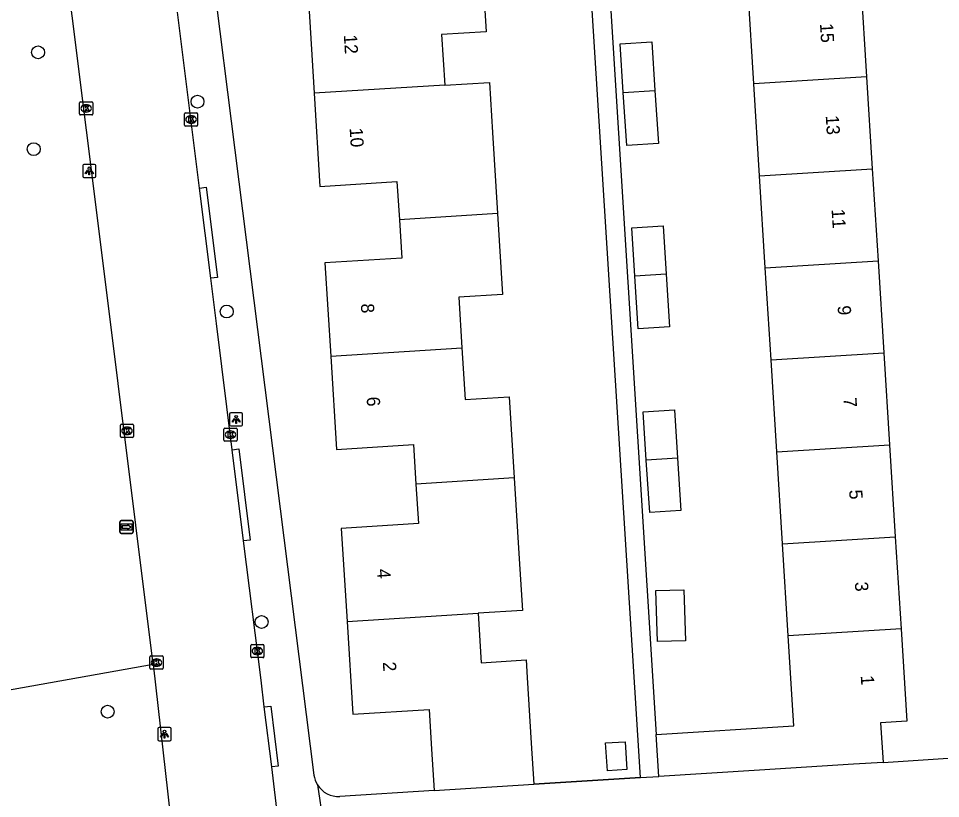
# Model space of a CAD drawing. Extents: x 159689 to 160786, y 387323 to 388339.
# Drawn here: x 160150.5 to 160220.6, y 388068.8 to 388128 of the extents above; entities that cross this region are included whole.
import ezdxf

# ---------------------------------------------------------------- set-up
doc = ezdxf.new("R2010")
doc.units = 0
for name, color, linetype in [('IMGEO_Berm_groen', 7, 'Continuous'), ('IMGEO_Boom', 7, 'Continuous'), ('IMGEO_Kolk', 7, 'Continuous'), ('IMGEO_Lichtpunt', 7, 'Continuous'), ('IMGEO_Muur', 7, 'Continuous'), ('IMGEO_Pand', 7, 'Continuous'), ('IMGEO_Pand_nummerreeks', 7, 'Continuous'), ('IMGEO_Rijbaan_lokaal_gesloten', 7, 'Continuous'), ('IMGEO_Voetpad_open', 7, 'Continuous'), ('IMGEO_Wegwijzer', 7, 'Continuous')]:
    doc.layers.add(name, color=color, linetype=linetype)

msp = doc.modelspace()

# ---------------------------------------------------------------- linework, layer by layer
at = {"layer": 'IMGEO_Berm_groen'}
msp.add_lwpolyline([(160145.16, 388076.181), (160160.785, 388078.981)], dxfattribs=at)
at = {"layer": 'IMGEO_Boom'}
for centre in [(160152.037, 388125.433), (160164.139, 388121.692), (160151.709, 388118.086), (160166.361, 388105.751), (160169.007, 388082.18), (160157.319, 388075.366)]:
    msp.add_circle(centre, 0.489, dxfattribs=at)
at = {"layer": 'IMGEO_Kolk'}
for p, q in [((160155.184, 388120.753), (160155.184, 388121.605)), ((160155.259, 388121.679), (160156.111, 388121.679)), ((160155.672, 388121.459), (160155.697, 388121.459)), ((160156.185, 388121.605), (160156.185, 388120.753)), ((160156.111, 388120.679), (160155.259, 388120.679)), ((160155.695, 388120.899), (160155.67, 388120.899)), ((160163.152, 388119.91), (160163.152, 388120.762)), ((160163.227, 388120.836), (160164.079, 388120.836)), ((160163.64, 388120.616), (160163.665, 388120.616)), ((160164.153, 388120.762), (160164.153, 388119.91)), ((160164.079, 388119.836), (160163.227, 388119.836)), ((160163.663, 388120.056), (160163.638, 388120.056)), ((160158.29, 388096.267), (160158.29, 388097.119)), ((160158.365, 388097.193), (160159.217, 388097.193)), ((160158.778, 388096.973), (160158.803, 388096.973)), ((160159.291, 388097.119), (160159.291, 388096.267)), ((160166.144, 388095.976), (160166.144, 388096.828)), ((160166.219, 388096.902), (160167.071, 388096.902)), ((160167.145, 388096.828), (160167.145, 388095.976)), ((160159.217, 388096.193), (160158.365, 388096.193)), ((160158.801, 388096.413), (160158.776, 388096.413)), ((160166.655, 388096.122), (160166.63, 388096.122)), ((160166.632, 388096.682), (160166.657, 388096.682)), ((160167.071, 388095.902), (160166.219, 388095.902)), ((160168.187, 388079.543), (160168.187, 388080.395)), ((160168.262, 388080.469), (160169.114, 388080.469)), ((160168.675, 388080.249), (160168.7, 388080.249)), ((160169.188, 388080.395), (160169.188, 388079.543)), ((160160.527, 388078.669), (160160.527, 388079.521)), ((160160.602, 388079.595), (160161.454, 388079.595)), ((160161.015, 388079.375), (160161.04, 388079.375)), ((160161.528, 388079.521), (160161.528, 388078.669)), ((160169.114, 388079.469), (160168.262, 388079.469)), ((160168.698, 388079.689), (160168.673, 388079.689)), ((160161.454, 388078.595), (160160.602, 388078.595)), ((160161.038, 388078.815), (160161.013, 388078.815))]:
    msp.add_line(p, q, dxfattribs=at)
for points in [[(160155.184, 388120.753), (160155.184, 388121.605)], [(160155.259, 388121.679), (160156.111, 388121.679)], [(160155.505, 388121.379), (160155.628, 388121.379), (160155.628, 388121.228), (160155.758, 388121.379), (160155.922, 388121.379), (160155.776, 388121.228), (160155.929, 388120.979), (160155.777, 388120.979), (160155.692, 388121.143), (160155.628, 388121.076), (160155.628, 388120.979), (160155.505, 388120.979), (160155.505, 388121.379)], [(160156.185, 388121.605), (160156.185, 388120.753)], [(160156.111, 388120.679), (160155.259, 388120.679)], [(160163.152, 388119.91), (160163.152, 388120.762)], [(160163.227, 388120.836), (160164.079, 388120.836)], [(160163.473, 388120.536), (160163.596, 388120.536), (160163.596, 388120.385), (160163.726, 388120.536), (160163.89, 388120.536), (160163.744, 388120.385), (160163.897, 388120.136), (160163.745, 388120.136), (160163.66, 388120.3), (160163.596, 388120.233), (160163.596, 388120.136), (160163.473, 388120.136), (160163.473, 388120.536)], [(160164.153, 388120.762), (160164.153, 388119.91)], [(160164.079, 388119.836), (160163.227, 388119.836)], [(160158.29, 388096.267), (160158.29, 388097.119)], [(160158.365, 388097.193), (160159.217, 388097.193)], [(160158.611, 388096.893), (160158.734, 388096.893), (160158.734, 388096.742), (160158.864, 388096.893), (160159.028, 388096.893), (160158.882, 388096.742), (160159.035, 388096.493), (160158.883, 388096.493), (160158.798, 388096.657), (160158.734, 388096.59), (160158.734, 388096.493), (160158.611, 388096.493), (160158.611, 388096.893)], [(160159.291, 388097.119), (160159.291, 388096.267)], [(160166.144, 388095.976), (160166.144, 388096.828)], [(160166.219, 388096.902), (160167.071, 388096.902)], [(160167.145, 388096.828), (160167.145, 388095.976)], [(160159.217, 388096.193), (160158.365, 388096.193)], [(160166.465, 388096.602), (160166.588, 388096.602), (160166.588, 388096.451), (160166.718, 388096.602), (160166.882, 388096.602), (160166.736, 388096.451), (160166.889, 388096.202), (160166.737, 388096.202), (160166.652, 388096.366), (160166.588, 388096.299), (160166.588, 388096.202), (160166.465, 388096.202), (160166.465, 388096.602)], [(160167.071, 388095.902), (160166.219, 388095.902)], [(160168.187, 388079.543), (160168.187, 388080.395)], [(160168.262, 388080.469), (160169.114, 388080.469)], [(160168.508, 388080.169), (160168.631, 388080.169), (160168.631, 388080.018), (160168.761, 388080.169), (160168.925, 388080.169), (160168.779, 388080.018), (160168.932, 388079.769), (160168.78, 388079.769), (160168.695, 388079.933), (160168.631, 388079.866), (160168.631, 388079.769), (160168.508, 388079.769), (160168.508, 388080.169)], [(160169.188, 388080.395), (160169.188, 388079.543)], [(160160.527, 388078.669), (160160.527, 388079.521)], [(160160.602, 388079.595), (160161.454, 388079.595)], [(160160.848, 388079.295), (160160.971, 388079.295), (160160.971, 388079.144), (160161.101, 388079.295), (160161.265, 388079.295), (160161.119, 388079.144), (160161.272, 388078.895), (160161.12, 388078.895), (160161.035, 388079.059), (160160.971, 388078.992), (160160.971, 388078.895), (160160.848, 388078.895), (160160.848, 388079.295)], [(160161.528, 388079.521), (160161.528, 388078.669)], [(160169.114, 388079.469), (160168.262, 388079.469)], [(160161.454, 388078.595), (160160.602, 388078.595)]]:
    msp.add_lwpolyline(points, dxfattribs=at)
for centre, start, end in [((160155.261, 388121.603), 91.55205, 178.44795), ((160155.261, 388121.603), 91.55205, 178.44795), ((160156.109, 388121.603), 1.55205, 88.44795), ((160156.109, 388121.603), 1.55205, 88.44795), ((160155.261, 388120.755), 181.55205, 268.44795), ((160155.261, 388120.755), 181.55205, 268.44795), ((160156.109, 388120.755), 271.55205, 358.44795), ((160156.109, 388120.755), 271.55205, 358.44795), ((160163.229, 388120.76), 91.55205, 178.44795), ((160163.229, 388120.76), 91.55205, 178.44795), ((160164.077, 388120.76), 1.55205, 88.44795), ((160164.077, 388120.76), 1.55205, 88.44795), ((160163.229, 388119.912), 181.55205, 268.44795), ((160163.229, 388119.912), 181.55205, 268.44795), ((160164.077, 388119.912), 271.55205, 358.44795), ((160164.077, 388119.912), 271.55205, 358.44795), ((160158.367, 388097.117), 91.55205, 178.44795), ((160158.367, 388097.117), 91.55205, 178.44795), ((160159.215, 388097.117), 1.55205, 88.44795), ((160159.215, 388097.117), 1.55205, 88.44795), ((160166.221, 388096.826), 91.55205, 178.44795), ((160166.221, 388096.826), 91.55205, 178.44795), ((160167.069, 388096.826), 1.55205, 88.44795), ((160167.069, 388096.826), 1.55205, 88.44795), ((160158.367, 388096.269), 181.55205, 268.44795), ((160158.367, 388096.269), 181.55205, 268.44795), ((160159.215, 388096.269), 271.55205, 358.44795), ((160159.215, 388096.269), 271.55205, 358.44795), ((160166.221, 388095.978), 181.55205, 268.44795), ((160166.221, 388095.978), 181.55205, 268.44795), ((160167.069, 388095.978), 271.55205, 358.44795), ((160167.069, 388095.978), 271.55205, 358.44795), ((160168.264, 388080.393), 91.55205, 178.44795), ((160168.264, 388080.393), 91.55205, 178.44795), ((160169.112, 388080.393), 1.55205, 88.44795), ((160169.112, 388080.393), 1.55205, 88.44795), ((160160.604, 388079.519), 91.55205, 178.44795), ((160160.604, 388079.519), 91.55205, 178.44795), ((160161.452, 388079.519), 1.55205, 88.44795), ((160161.452, 388079.519), 1.55205, 88.44795), ((160168.264, 388079.545), 181.55205, 268.44795), ((160168.264, 388079.545), 181.55205, 268.44795), ((160169.112, 388079.545), 271.55205, 358.44795), ((160169.112, 388079.545), 271.55205, 358.44795), ((160160.604, 388078.671), 181.55205, 268.44795), ((160160.604, 388078.671), 181.55205, 268.44795), ((160161.452, 388078.671), 271.55205, 358.44795), ((160161.452, 388078.671), 271.55205, 358.44795)]:
    msp.add_arc(centre, 0.0765, start, end, dxfattribs=at)
for centre, major_axis, ratio, start_param, end_param in [((160155.671, 388121.179), (-0.387, 0.002), 0.722429, 4.712389, 7.853982), ((160155.696, 388121.179), (-0.39, 0.002), 0.717154, 1.570796, 4.712389), ((160163.639, 388120.336), (-0.387, 0.002), 0.722429, 4.712389, 7.853982), ((160163.664, 388120.336), (-0.39, 0.002), 0.717154, 1.570796, 4.712389), ((160158.777, 388096.693), (-0.387, 0.002), 0.722429, 4.712389, 7.853982), ((160158.802, 388096.693), (-0.39, 0.002), 0.717154, 1.570796, 4.712389), ((160166.631, 388096.402), (-0.387, 0.002), 0.722429, 4.712389, 7.853982), ((160166.656, 388096.402), (-0.39, 0.002), 0.717154, 1.570796, 4.712389), ((160168.674, 388079.969), (-0.387, 0.002), 0.722429, 4.712389, 7.853982), ((160168.699, 388079.969), (-0.39, 0.002), 0.717154, 1.570796, 4.712389), ((160161.014, 388079.095), (-0.387, 0.002), 0.722429, 4.712389, 7.853982), ((160161.039, 388079.095), (-0.39, 0.002), 0.717154, 1.570796, 4.712389)]:
    msp.add_ellipse(centre, major_axis=major_axis, ratio=ratio, start_param=start_param, end_param=end_param, dxfattribs=at)
at = {"layer": 'IMGEO_Lichtpunt'}
for p, q in [((160155.426, 388116.831), (160155.426, 388116.024)), ((160155.426, 388116.831), (160155.426, 388116.024)), ((160156.328, 388116.926), (160155.52, 388116.926)), ((160156.328, 388116.926), (160155.52, 388116.926)), ((160156.422, 388116.024), (160156.422, 388116.831)), ((160156.422, 388116.024), (160156.422, 388116.831)), ((160155.52, 388115.93), (160156.328, 388115.93)), ((160155.52, 388115.93), (160156.328, 388115.93)), ((160166.574, 388097.967), (160166.574, 388097.16)), ((160166.574, 388097.967), (160166.574, 388097.16)), ((160167.476, 388098.062), (160166.668, 388098.062)), ((160167.476, 388098.062), (160166.668, 388098.062)), ((160167.57, 388097.16), (160167.57, 388097.967)), ((160167.57, 388097.16), (160167.57, 388097.967)), ((160166.668, 388097.066), (160167.476, 388097.066)), ((160166.668, 388097.066), (160167.476, 388097.066)), ((160161.139, 388074.062), (160161.139, 388073.255)), ((160161.139, 388074.062), (160161.139, 388073.255)), ((160162.041, 388074.157), (160161.233, 388074.157)), ((160162.041, 388074.157), (160161.233, 388074.157)), ((160162.135, 388073.255), (160162.135, 388074.062)), ((160162.135, 388073.255), (160162.135, 388074.062)), ((160161.233, 388073.161), (160162.041, 388073.161)), ((160161.233, 388073.161), (160162.041, 388073.161))]:
    msp.add_line(p, q, dxfattribs=at)
for points in [[(160155.8, 388116.495), (160155.839, 388116.467), (160155.651, 388116.205), (160155.613, 388116.232), (160155.8, 388116.495)], [(160155.902, 388116.447), (160155.949, 388116.447), (160155.949, 388116.125), (160155.902, 388116.125), (160155.902, 388116.447)], [(160156.012, 388116.467), (160156.05, 388116.494), (160156.237, 388116.232), (160156.198, 388116.204), (160156.012, 388116.467)], [(160166.948, 388097.631), (160166.987, 388097.603), (160166.799, 388097.341), (160166.761, 388097.368), (160166.948, 388097.631)], [(160167.05, 388097.583), (160167.097, 388097.583), (160167.097, 388097.261), (160167.05, 388097.261), (160167.05, 388097.583)], [(160167.16, 388097.603), (160167.198, 388097.63), (160167.385, 388097.368), (160167.346, 388097.34), (160167.16, 388097.603)], [(160161.513, 388073.726), (160161.552, 388073.698), (160161.364, 388073.436), (160161.326, 388073.463), (160161.513, 388073.726)], [(160161.615, 388073.678), (160161.662, 388073.678), (160161.662, 388073.356), (160161.615, 388073.356), (160161.615, 388073.678)], [(160161.725, 388073.698), (160161.763, 388073.725), (160161.95, 388073.463), (160161.911, 388073.435), (160161.725, 388073.698)]]:
    msp.add_lwpolyline(points, dxfattribs=at)
for centre in [(160155.925, 388116.629), (160167.073, 388097.765), (160161.638, 388073.86)]:
    msp.add_circle(centre, 0.0994, dxfattribs=at)
for centre, start, end in [((160155.52, 388116.831), 90, 180), ((160155.52, 388116.831), 90, 180), ((160156.328, 388116.831), 0, 90), ((160156.328, 388116.831), 0, 90), ((160155.52, 388116.024), 180, 270), ((160155.52, 388116.024), 180, 270), ((160156.328, 388116.024), 270, 0), ((160156.328, 388116.024), 270, 360), ((160166.668, 388097.967), 90, 180), ((160166.668, 388097.967), 90, 180), ((160167.476, 388097.967), 0, 90), ((160167.476, 388097.967), 0, 90), ((160166.668, 388097.16), 180, 270), ((160166.668, 388097.16), 180, 270), ((160167.476, 388097.16), 270, 0), ((160167.476, 388097.16), 270, 360), ((160161.233, 388074.062), 90, 180), ((160161.233, 388074.062), 90, 180), ((160162.041, 388074.062), 0, 90), ((160162.041, 388074.062), 0, 90), ((160161.233, 388073.255), 180, 270), ((160161.233, 388073.255), 180, 270), ((160162.041, 388073.255), 270, 0), ((160162.041, 388073.255), 270, 360)]:
    msp.add_arc(centre, 0.0946, start, end, dxfattribs=at)
at = {"layer": 'IMGEO_Muur'}
msp.add_lwpolyline([(160197.779, 388070.357), (160189.678, 388069.849)], dxfattribs=at)
at = {"layer": 'IMGEO_Pand'}
for points in [[(160185.677, 388133.171), (160186.062, 388126.992), (160182.674, 388126.781), (160182.913, 388122.946)], [(160178.211, 388132.708), (160178.394, 388129.769), (160172.559, 388129.405), (160172.999, 388122.33)], [(160206.378, 388123.038), (160205.94, 388130.05), (160209.512, 388130.274), (160214.502, 388130.586), (160214.94, 388123.574)], [(160196.473, 388122.38), (160196.235, 388126.074), (160198.637, 388126.229), (160198.876, 388122.531)], [(160214.94, 388123.574), (160206.378, 388123.038)], [(160214.94, 388123.574), (160215.377, 388116.587)], [(160182.913, 388122.946), (160172.999, 388122.33)], [(160182.913, 388122.946), (160186.307, 388123.157), (160186.544, 388119.347), (160186.928, 388113.187)], [(160206.815, 388116.051), (160206.378, 388123.038)], [(160172.999, 388122.33), (160173.439, 388115.257), (160179.287, 388115.621), (160179.467, 388112.718)], [(160198.876, 388122.531), (160199.136, 388118.503), (160196.734, 388118.348), (160196.473, 388122.38)], [(160196.473, 388122.38), (160198.876, 388122.531)], [(160206.815, 388116.051), (160215.377, 388116.587)], [(160215.377, 388116.587), (160215.814, 388109.601)], [(160207.252, 388109.065), (160206.815, 388116.051)], [(160186.928, 388113.187), (160179.467, 388112.718)], [(160186.928, 388113.187), (160187.31, 388107.056), (160183.978, 388106.848), (160184.218, 388102.99)], [(160179.467, 388112.718), (160179.648, 388109.815), (160173.821, 388109.452), (160174.262, 388102.368)], [(160197.345, 388108.445), (160197.109, 388112.101), (160199.491, 388112.255), (160199.727, 388108.594)], [(160207.252, 388109.065), (160215.814, 388109.601)], [(160215.814, 388109.601), (160216.251, 388102.615)], [(160199.727, 388108.594), (160199.985, 388104.587), (160197.604, 388104.433), (160197.345, 388108.445)], [(160199.727, 388108.594), (160197.345, 388108.445)], [(160207.689, 388102.079), (160207.252, 388109.065)], [(160174.262, 388102.368), (160184.218, 388102.99)], [(160174.262, 388102.368), (160174.703, 388095.284), (160180.542, 388095.648), (160180.728, 388092.65)], [(160184.218, 388102.99), (160184.462, 388099.079), (160187.801, 388099.286), (160188.185, 388093.116)], [(160207.689, 388102.079), (160216.251, 388102.615)], [(160216.251, 388102.615), (160216.688, 388095.628)], [(160208.126, 388095.092), (160207.689, 388102.079)], [(160198.219, 388094.472), (160197.983, 388098.128), (160200.357, 388098.281), (160200.593, 388094.62)], [(160208.126, 388095.092), (160216.688, 388095.628)], [(160216.688, 388095.628), (160217.125, 388088.642)], [(160200.593, 388094.62), (160200.85, 388090.641), (160198.476, 388090.488), (160198.219, 388094.472)], [(160200.593, 388094.62), (160198.219, 388094.472)], [(160208.562, 388088.106), (160208.126, 388095.092)], [(160180.728, 388092.65), (160180.915, 388089.649), (160175.053, 388089.284), (160175.493, 388082.225)], [(160188.185, 388093.116), (160180.728, 388092.65)], [(160188.185, 388093.116), (160188.568, 388086.975), (160188.813, 388083.05), (160185.458, 388082.842)], [(160208.562, 388088.106), (160217.125, 388088.642)], [(160217.125, 388088.642), (160217.562, 388081.655)], [(160208.999, 388081.119), (160208.562, 388088.106)], [(160201.063, 388084.63), (160201.186, 388080.753), (160199.059, 388080.686), (160198.935, 388084.563), (160201.063, 388084.63)], [(160175.493, 388082.225), (160185.458, 388082.842)], [(160185.458, 388082.842), (160185.692, 388079.084), (160189.09, 388079.295), (160189.172, 388077.969), (160189.483, 388072.978), (160189.678, 388069.849)], [(160175.493, 388082.225), (160175.932, 388075.166), (160181.725, 388075.527), (160181.913, 388072.507), (160182.108, 388069.377)], [(160217.562, 388081.655), (160208.999, 388081.119)], [(160217.562, 388081.655), (160218, 388074.645), (160216.004, 388074.52), (160216.192, 388071.518)], [(160198.976, 388073.628), (160209.427, 388074.282), (160209.377, 388075.076), (160208.999, 388081.119)], [(160199.176, 388070.444), (160198.976, 388073.628)], [(160195.129, 388072.988), (160196.601, 388073.08), (160196.733, 388070.977), (160195.261, 388070.885), (160195.129, 388072.988)], [(160216.192, 388071.518), (160213.943, 388071.371), (160206.819, 388070.925), (160199.176, 388070.444)], [(160182.108, 388069.377), (160189.678, 388069.849)]]:
    msp.add_lwpolyline(points, dxfattribs=at)
at = {"layer": 'IMGEO_Rijbaan_lokaal_gesloten'}
for points in [[(160160.785, 388078.981), (160156.813, 388110.855), (160154.631, 388128.209), (160148.378, 388177.868), (160148.056, 388180.455)], [(160164.304, 388115.133), (160162.63, 388128.476)], [(160165.162, 388108.292), (160164.304, 388115.133)], [(160166.786, 388095.256), (160165.595, 388104.837), (160165.162, 388108.292)], [(160167.646, 388088.338), (160166.786, 388095.256)], [(160169.211, 388075.731), (160168.963, 388077.746), (160167.646, 388088.338)], [(160160.785, 388078.981), (160160.786, 388078.973), (160163.004, 388059.227), (160164.513, 388041.045), (160164.518, 388040.982)], [(160169.773, 388071.175), (160169.211, 388075.731)], [(160174.423, 388042.02), (160172.311, 388054.67), (160170.276, 388067.092), (160169.773, 388071.175)]]:
    msp.add_lwpolyline(points, dxfattribs=at)
at = {"layer": 'IMGEO_Voetpad_open'}
for points in [[(160197.779, 388070.357), (160190.01, 388193.783), (160181.81, 388193.267)], [(160157.662, 388191.738), (160159.285, 388178.9), (160172.985, 388070.553)], [(160220.402, 388132.213), (160195.393, 388130.64), (160198.976, 388073.628)], [(160164.304, 388115.133), (160164.8, 388115.19), (160165.658, 388108.349), (160165.162, 388108.292)], [(160166.786, 388095.256), (160167.282, 388095.313), (160168.142, 388088.395), (160167.646, 388088.338)], [(160169.211, 388075.731), (160169.707, 388075.786), (160170.269, 388071.23), (160169.773, 388071.175)], [(160216.192, 388071.518), (160224.188, 388072.039)], [(160189.678, 388069.849), (160197.779, 388070.357)], [(160197.779, 388070.357), (160199.176, 388070.444)], [(160173.246, 388069.814), (160174.531, 388061.159)], [(160182.108, 388069.377), (160174.959, 388068.93)]]:
    msp.add_lwpolyline(points, dxfattribs=at)
for centre, radius, start, end in [((160174.816, 388070.784), 1.846, 187.19565, 211.70875), ((160174.833, 388070.788), 1.862, 211.53872, 273.86895)]:
    msp.add_arc(centre, radius, start, end, dxfattribs=at)
at = {"layer": 'IMGEO_Wegwijzer'}
for p, q in [((160158.254, 388088.989), (160158.254, 388089.789)), ((160158.254, 388089.789), (160158.254, 388088.989)), ((160158.354, 388089.889), (160159.144, 388089.889)), ((160159.144, 388089.889), (160158.354, 388089.889)), ((160159.244, 388089.789), (160159.244, 388088.989)), ((160159.244, 388088.989), (160159.244, 388089.789)), ((160159.144, 388088.889), (160158.354, 388088.889)), ((160158.354, 388088.889), (160159.144, 388088.889))]:
    msp.add_line(p, q, dxfattribs=at)
for points in [[(160158.355, 388089.621), (160159.143, 388089.621), (160159.143, 388089.157), (160158.355, 388089.157), (160158.355, 388089.621)], [(160158.42, 388089.473), (160158.42, 388089.389), (160158.42, 388089.305), (160158.831, 388089.305), (160158.831, 388089.222), (160159.078, 388089.389), (160158.831, 388089.556), (160158.831, 388089.473), (160158.42, 388089.473)]]:
    msp.add_lwpolyline(points, dxfattribs=at)
for centre, start, end in [((160158.354, 388089.789), 90, 180), ((160158.354, 388089.789), 90, 180), ((160159.144, 388089.789), 0, 90), ((160159.144, 388089.789), 360, 90), ((160158.354, 388088.989), 180, 270), ((160158.354, 388088.989), 180, 270), ((160159.144, 388088.989), 270, 0), ((160159.144, 388088.989), 270, 0)]:
    msp.add_arc(centre, 0.1, start, end, dxfattribs=at)

# ---------------------------------------------------------------- texts
at = {"layer": 'IMGEO_Pand_nummerreeks'}
for s, rotation, p in [('15', 273.57806, (160211.4, 388127.619)), ('12', 273.55919, (160175.248, 388126.761)), ('13', 273.57806, (160211.838, 388120.626)), ('10', 273.55919, (160175.689, 388119.681)), ('11', 273.57806, (160212.283, 388113.519)), ('8', 273.56224, (160176.539, 388106.337)), ('9', 273.57806, (160212.741, 388106.182)), ('6', 273.56224, (160176.98, 388099.257)), ('7', 273.57806, (160213.178, 388099.189)), ('5', 273.57806, (160213.616, 388092.197)), ('4', 273.56359, (160177.77, 388086.187)), ('3', 273.57806, (160214.053, 388085.204)), ('2', 273.56269, (160178.21, 388079.129)), ('1', 273.57806, (160214.497, 388078.097))]:
    msp.add_text(s, height=1, rotation=rotation, dxfattribs=at).set_placement(p)

doc.saveas('drawing.dxf')
